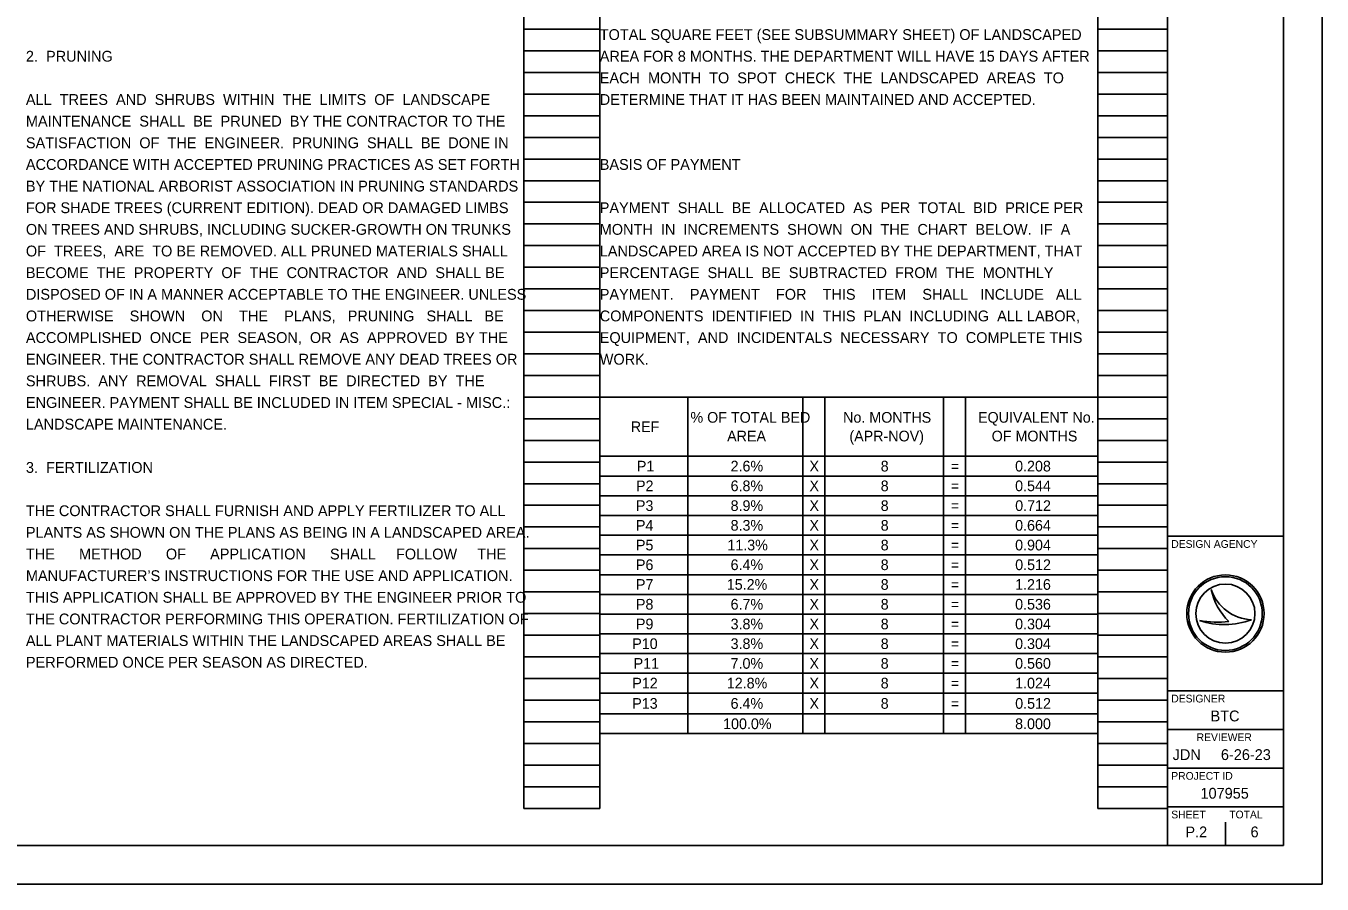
# Model space of a CAD drawing. Extents: x 0 to 34, y 0 to 22.
# Drawn here: x 17.24 to 34, y 0 to 11.1 of the extents above; entities that cross this region are included whole.
import ezdxf

# ---------------------------------------------------------------- set-up
doc = ezdxf.new("R2010")
doc.units = 0
for name, color, linetype in [('SH_Border', 7, 'Continuous'), ('SH_Cut_Line', 7, 'Continuous'), ('SH_Data', 7, 'Continuous'), ('SH_Text', 7, 'Continuous')]:
    doc.layers.add(name, color=color, linetype=linetype)

msp = doc.modelspace()

# ---------------------------------------------------------------- linework, layer by layer
at = {"layer": 'SH_Border'}
for p, q in [((32, 0.5), (32, 21.5)), ((32, 4.5), (33.5, 4.5)), ((32, 2.5), (33.5, 2.5)), ((32, 2), (33.5, 2)), ((32, 1.5), (33.5, 1.5)), ((32, 1), (33.5, 1))]:
    msp.add_line(p, q, dxfattribs=at)
msp.add_lwpolyline([(1.5, 21.5), (33.5, 21.5), (33.5, 0.5), (1.5, 0.5)], close=True, dxfattribs=at)
at = {"layer": 'SH_Cut_Line'}
msp.add_lwpolyline([(0, 0), (34, 0), (34, 22), (0, 22)], close=True, dxfattribs=at)
at = {"layer": 'SH_Data'}
for p, q in [((23.68, 0.98), (23.68, 21.14)), ((24.66, 0.98), (24.66, 21.14)), ((31.1, 0.98), (31.1, 21.14)), ((32, 0.98), (32, 21.14)), ((23.68, 11.06), (24.66, 11.06)), ((31.1, 11.06), (32, 11.06)), ((23.68, 10.78), (24.66, 10.78)), ((31.1, 10.78), (32, 10.78)), ((23.68, 10.5), (24.66, 10.5)), ((31.1, 10.5), (32, 10.5)), ((23.68, 10.22), (24.66, 10.22)), ((31.1, 10.22), (32, 10.22)), ((23.68, 9.94), (24.66, 9.94)), ((31.1, 9.94), (32, 9.94)), ((23.68, 9.66), (24.66, 9.66)), ((31.1, 9.66), (32, 9.66)), ((23.68, 9.38), (24.66, 9.38)), ((31.1, 9.38), (32, 9.38)), ((23.68, 9.1), (24.66, 9.1)), ((31.1, 9.1), (32, 9.1)), ((23.68, 8.82), (24.66, 8.82)), ((31.1, 8.82), (32, 8.82)), ((23.68, 8.54), (24.66, 8.54)), ((31.1, 8.54), (32, 8.54)), ((23.68, 8.26), (24.66, 8.26)), ((31.1, 8.26), (32, 8.26)), ((23.68, 7.98), (24.66, 7.98)), ((31.1, 7.98), (32, 7.98)), ((23.68, 7.7), (24.66, 7.7)), ((31.1, 7.7), (32, 7.7)), ((23.68, 7.42), (24.66, 7.42)), ((31.1, 7.42), (32, 7.42)), ((23.68, 7.14), (24.66, 7.14)), ((31.1, 7.14), (32, 7.14)), ((23.68, 6.86), (24.66, 6.86)), ((31.1, 6.86), (32, 6.86)), ((23.68, 6.58), (24.66, 6.58)), ((31.1, 6.58), (32, 6.58)), ((23.68, 6.3), (24.66, 6.3)), ((31.1, 6.3), (32, 6.3)), ((23.68, 6.02), (24.66, 6.02)), ((31.1, 6.02), (32, 6.02)), ((23.68, 5.74), (24.66, 5.74)), ((31.1, 5.74), (32, 5.74)), ((23.68, 5.46), (24.66, 5.46)), ((31.1, 5.46), (32, 5.46)), ((23.68, 5.18), (24.66, 5.18)), ((31.1, 5.18), (32, 5.18)), ((23.68, 4.9), (24.66, 4.9)), ((31.1, 4.9), (32, 4.9)), ((23.68, 4.62), (24.66, 4.62)), ((31.1, 4.62), (32, 4.62)), ((23.68, 4.34), (24.66, 4.34)), ((31.1, 4.34), (32, 4.34)), ((23.68, 4.06), (24.66, 4.06)), ((31.1, 4.06), (32, 4.06)), ((23.68, 3.78), (24.66, 3.78)), ((31.1, 3.78), (32, 3.78)), ((32.567, 3.81), (32.567, 3.81)), ((23.68, 3.5), (24.66, 3.5)), ((31.1, 3.5), (32, 3.5)), ((32.417, 3.41), (32.417, 3.41)), ((32.75, 3.5), (32.75, 3.5)), ((33.087, 3.419), (33.087, 3.419)), ((23.68, 3.22), (24.66, 3.22)), ((31.1, 3.22), (32, 3.22)), ((23.68, 2.94), (24.66, 2.94)), ((31.1, 2.94), (32, 2.94)), ((23.68, 2.66), (24.66, 2.66)), ((31.1, 2.66), (32, 2.66)), ((23.68, 2.38), (24.66, 2.38)), ((31.1, 2.38), (32, 2.38)), ((23.68, 2.1), (24.66, 2.1)), ((31.1, 2.1), (32, 2.1)), ((23.68, 1.82), (24.66, 1.82)), ((31.1, 1.82), (32, 1.82)), ((23.68, 1.54), (24.66, 1.54)), ((31.1, 1.54), (32, 1.54)), ((23.68, 1.26), (24.66, 1.26)), ((31.1, 1.26), (32, 1.26)), ((23.68, 0.98), (24.66, 0.98)), ((31.1, 0.98), (32, 0.98)), ((32.375, 0.675), (32.375, 0.675)), ((32.75, 0.5), (32.75, 0.8))]:
    msp.add_line(p, q, dxfattribs=at)
for radius in [0.5, 0.477, 0.477, 0.382]:
    msp.add_circle((32.75, 3.5), radius, dxfattribs=at)
for centre, radius, start, end in [((33.116, 3.998), 0.58, 198.9257, 198.9319), ((33.347, 3.97), 0.796, 191.6379, 191.6421), ((33.116, 3.998), 0.58, 198.9319, 267.1657), ((33.347, 3.97), 0.796, 191.6421, 226.0947), ((32.739, 4.37), 1.013, 251.4576, 290.0832), ((32.648, 4.654), 1.266, 259.4964, 259.4995), ((32.739, 4.37), 1.013, 251.4527, 251.4576), ((32.648, 4.654), 1.266, 259.4995, 276.6672)]:
    msp.add_arc(centre, radius, start, end, dxfattribs=at)
at = {"layer": 'SH_Text'}
for p, q in [((24.66, 6.3), (31.1, 6.3)), ((24.66, 6.3), (24.66, 1.947)), ((25.801, 6.3), (25.801, 1.947)), ((27.287, 6.3), (27.287, 1.947)), ((27.572, 6.3), (27.572, 1.947)), ((29.103, 6.3), (29.103, 1.947)), ((29.389, 6.3), (29.389, 1.947)), ((31.1, 6.3), (31.1, 1.947)), ((24.66, 5.534), (31.1, 5.534)), ((24.66, 5.279), (31.1, 5.279)), ((24.66, 5.024), (31.1, 5.024)), ((24.66, 4.769), (31.1, 4.769)), ((24.66, 4.514), (31.1, 4.514)), ((24.66, 4.258), (31.1, 4.258)), ((24.66, 4.003), (31.1, 4.003)), ((24.66, 3.748), (31.1, 3.748)), ((24.66, 3.493), (31.1, 3.493)), ((24.66, 3.238), (31.1, 3.238)), ((24.66, 2.982), (31.1, 2.982)), ((24.66, 2.727), (31.1, 2.727)), ((24.66, 2.472), (31.1, 2.472)), ((24.66, 2.202), (31.1, 2.202)), ((24.66, 1.947), (31.1, 1.947))]:
    msp.add_line(p, q, dxfattribs=at)

# ---------------------------------------------------------------- texts
at = {"layer": 'SH_Data'}
for s, height, p in [('DESIGN AGENCY', 0.1, (32.05, 4.35)), ('DESIGNER', 0.1, (32.05, 2.35)), ('BTC', 0.14, (32.558, 2.105)), ('REVIEWER', 0.1, (32.378, 1.85)), ('JDN', 0.14, (32.068, 1.605)), ('6-26-23', 0.14, (32.692, 1.605)), ('PROJECT ID', 0.1, (32.05, 1.35)), ('107955', 0.14, (32.428, 1.105)), ('SHEET', 0.1, (32.05, 0.85)), ('TOTAL', 0.1, (32.8, 0.85)), ('P.2', 0.14, (32.233, 0.605)), ('6', 0.14, (33.075, 0.605))]:
    msp.add_text(s, height=height, dxfattribs=at).set_placement(p)
at = {"layer": 'SH_Text'}
for s, height, p in [('TOTAL SQUARE FEET (SEE SUBSUMMARY SHEET) OF LANDSCAPED', 0.14, (24.66, 10.92)), ('2.  PRUNING', 0.14, (17.24, 10.64)), ('AREA FOR 8 MONTHS. THE DEPARTMENT WILL HAVE 15 DAYS AFTER', 0.14, (24.66, 10.64)), ('EACH  MONTH  TO  SPOT  CHECK  THE  LANDSCAPED  AREAS  TO', 0.14, (24.66, 10.36)), ('ALL  TREES  AND  SHRUBS  WITHIN  THE  LIMITS  OF  LANDSCAPE', 0.14, (17.24, 10.08)), ('DETERMINE THAT IT HAS BEEN MAINTAINED AND ACCEPTED.', 0.14, (24.66, 10.08)), ('MAINTENANCE  SHALL  BE  PRUNED  BY THE CONTRACTOR TO THE', 0.14, (17.24, 9.8)), ('SATISFACTION  OF  THE  ENGINEER.  PRUNING  SHALL  BE  DONE IN', 0.14, (17.24, 9.52)), ('ACCORDANCE WITH ACCEPTED PRUNING PRACTICES AS SET FORTH', 0.14, (17.24, 9.24)), ('BASIS OF PAYMENT', 0.14, (24.66, 9.24)), ('BY THE NATIONAL ARBORIST ASSOCIATION IN PRUNING STANDARDS', 0.14, (17.24, 8.96)), ('FOR SHADE TREES (CURRENT EDITION). DEAD OR DAMAGED LIMBS', 0.14, (17.24, 8.68)), ('PAYMENT  SHALL  BE  ALLOCATED  AS  PER  TOTAL  BID  PRICE PER', 0.14, (24.66, 8.68)), ('ON TREES AND SHRUBS, INCLUDING SUCKER-GROWTH ON TRUNKS', 0.14, (17.24, 8.4)), ('MONTH  IN  INCREMENTS  SHOWN  ON  THE  CHART  BELOW.  IF  A', 0.14, (24.66, 8.4)), ('OF  TREES,  ARE  TO BE REMOVED. ALL PRUNED MATERIALS SHALL', 0.14, (17.24, 8.12)), ('LANDSCAPED AREA IS NOT ACCEPTED BY THE DEPARTMENT, THAT', 0.14, (24.66, 8.12)), ('BECOME  THE  PROPERTY  OF  THE  CONTRACTOR  AND  SHALL BE', 0.14, (17.24, 7.84)), ('PERCENTAGE  SHALL  BE  SUBTRACTED  FROM  THE  MONTHLY', 0.14, (24.66, 7.84)), ('DISPOSED OF IN A MANNER ACCEPTABLE TO THE ENGINEER. UNLESS', 0.14, (17.24, 7.56)), ('PAYMENT.    PAYMENT    FOR    THIS    ITEM    SHALL   INCLUDE   ALL', 0.14, (24.66, 7.56)), ('OTHERWISE    SHOWN    ON    THE    PLANS,   PRUNING   SHALL   BE', 0.14, (17.24, 7.28)), ('COMPONENTS  IDENTIFIED  IN  THIS  PLAN  INCLUDING  ALL LABOR,', 0.14, (24.66, 7.28)), ('ACCOMPLISHED  ONCE  PER  SEASON,  OR  AS  APPROVED  BY THE', 0.14, (17.24, 7)), ('EQUIPMENT,  AND  INCIDENTALS  NECESSARY  TO  COMPLETE THIS', 0.14, (24.66, 7)), ('ENGINEER. THE CONTRACTOR SHALL REMOVE ANY DEAD TREES OR', 0.14, (17.24, 6.72)), ('WORK.', 0.14, (24.66, 6.72)), ('SHRUBS.  ANY  REMOVAL  SHALL  FIRST  BE  DIRECTED  BY  THE', 0.14, (17.24, 6.44)), ('ENGINEER. PAYMENT SHALL BE INCLUDED IN ITEM SPECIAL - MISC.:', 0.14, (17.24, 6.16)), ('% OF TOTAL BED ', 0.13811, (25.833, 5.969)), ('No. MONTHS', 0.1381, (27.807, 5.969)), ('EQUIVALENT No. ', 0.13811, (29.551, 5.969)), ('LANDSCAPE MAINTENANCE.', 0.14, (17.24, 5.88)), ('REF', 0.1381, (25.061, 5.848)), ('(APR-NOV)', 0.1381, (27.888, 5.727)), ('OF MONTHS', 0.1381, (29.728, 5.727)), ('AREA', 0.1381, (26.307, 5.727)), ('3.  FERTILIZATION', 0.14, (17.24, 5.32)), ('P1', 0.1381, (25.14, 5.338)), ('2.6%', 0.1381, (26.352, 5.338)), ('X', 0.138, (27.372, 5.338)), ('8', 0.138, (28.293, 5.338)), ('=', 0.138, (29.2, 5.338)), ('0.208', 0.1381, (30.031, 5.338)), ('P2', 0.1381, (25.129, 5.083)), ('6.8%', 0.1381, (26.352, 5.083)), ('X', 0.138, (27.372, 5.083)), ('8', 0.138, (28.293, 5.083)), ('0.544', 0.1381, (30.031, 5.083)), ('=', 0.138, (29.2, 5.083)), ('THE CONTRACTOR SHALL FURNISH AND APPLY FERTILIZER TO ALL', 0.14, (17.24, 4.76)), ('P3', 0.1381, (25.128, 4.827)), ('8.9%', 0.1381, (26.352, 4.827)), ('X', 0.138, (27.372, 4.827)), ('8', 0.138, (28.293, 4.827)), ('=', 0.138, (29.2, 4.827)), ('0.712', 0.1381, (30.032, 4.827)), ('P4', 0.1381, (25.128, 4.572)), ('8.3%', 0.1381, (26.352, 4.572)), ('X', 0.138, (27.372, 4.572)), ('8', 0.138, (28.293, 4.572)), ('0.664', 0.1381, (30.031, 4.572)), ('PLANTS AS SHOWN ON THE PLANS AS BEING IN A LANDSCAPED AREA.', 0.14, (17.24, 4.48)), ('=', 0.138, (29.2, 4.572)), ('P5', 0.1381, (25.128, 4.317)), ('11.3%', 0.1381, (26.31, 4.317)), ('X', 0.138, (27.372, 4.317)), ('8', 0.138, (28.293, 4.317)), ('=', 0.138, (29.2, 4.317)), ('0.904', 0.1381, (30.031, 4.317)), ('THE      METHOD      OF      APPLICATION      SHALL     FOLLOW     THE', 0.14, (17.24, 4.2)), ('P6', 0.1381, (25.128, 4.062)), ('6.4%', 0.1381, (26.352, 4.062)), ('X', 0.138, (27.372, 4.062)), ('8', 0.138, (28.293, 4.062)), ('0.512', 0.1381, (30.032, 4.062)), ('MANUFACTURER’S INSTRUCTIONS FOR THE USE AND APPLICATION.', 0.14, (17.24, 3.92)), ('=', 0.138, (29.2, 4.062)), ('P7', 0.1381, (25.128, 3.807)), ('15.2%', 0.1381, (26.303, 3.807)), ('X', 0.138, (27.372, 3.807)), ('8', 0.138, (28.293, 3.807)), ('=', 0.138, (29.2, 3.807)), ('1.216', 0.1381, (30.031, 3.807)), ('THIS APPLICATION SHALL BE APPROVED BY THE ENGINEER PRIOR TO', 0.14, (17.24, 3.64)), ('P8', 0.1381, (25.128, 3.551)), ('6.7%', 0.1381, (26.352, 3.551)), ('X', 0.138, (27.372, 3.551)), ('8', 0.138, (28.293, 3.551)), ('0.536', 0.1381, (30.031, 3.551)), ('=', 0.138, (29.2, 3.551)), ('THE CONTRACTOR PERFORMING THIS OPERATION. FERTILIZATION OF', 0.14, (17.24, 3.36)), ('P9', 0.1381, (25.128, 3.296)), ('3.8%', 0.1381, (26.352, 3.296)), ('X', 0.138, (27.372, 3.296)), ('8', 0.138, (28.293, 3.296)), ('=', 0.138, (29.2, 3.296)), ('0.304', 0.1381, (30.031, 3.296)), ('ALL PLANT MATERIALS WITHIN THE LANDSCAPED AREAS SHALL BE', 0.14, (17.24, 3.08)), ('P10', 0.1381, (25.08, 3.041)), ('3.8%', 0.1381, (26.352, 3.041)), ('X', 0.138, (27.372, 3.041)), ('8', 0.138, (28.293, 3.041)), ('=', 0.138, (29.2, 3.041)), ('0.304', 0.1381, (30.031, 3.041)), ('PERFORMED ONCE PER SEASON AS DIRECTED.', 0.14, (17.24, 2.8)), ('P11', 0.1381, (25.098, 2.786)), ('7.0%', 0.1381, (26.352, 2.786)), ('X', 0.138, (27.372, 2.786)), ('8', 0.138, (28.293, 2.786)), ('=', 0.138, (29.2, 2.786)), ('0.560', 0.1381, (30.031, 2.786)), ('P12', 0.1381, (25.081, 2.531)), ('12.8%', 0.1381, (26.303, 2.531)), ('X', 0.138, (27.372, 2.531)), ('8', 0.138, (28.293, 2.531)), ('=', 0.138, (29.2, 2.531)), ('1.024', 0.1381, (30.031, 2.531)), ('P13', 0.1381, (25.08, 2.268)), ('6.4%', 0.1381, (26.352, 2.268)), ('X', 0.138, (27.372, 2.268)), ('8', 0.138, (28.293, 2.268)), ('=', 0.138, (29.2, 2.268)), ('0.512', 0.1381, (30.032, 2.268)), ('100.0%', 0.1381, (26.255, 2.005)), ('8.000', 0.1381, (30.031, 2.005))]:
    msp.add_text(s, height=height, dxfattribs=at).set_placement(p)

doc.saveas('drawing.dxf')
